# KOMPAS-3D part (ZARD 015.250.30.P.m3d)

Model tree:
1. Плоскость XY
2. Плоскость ZX
3. Плоскость ZY
4. Ось X
5. Ось Y
6. Ось Z
7. Начало координат
8. Смещенная плоскость:1
     Расстояние = 100
9. Смещенная плоскость:2
     Расстояние = 100
10. Смещенная плоскость:3
     Расстояние = 105
11. Смещенная плоскость:4
     Расстояние = 105
12. Булева операция:1
13. Булева операция:2
14. Булева операция:3
15. Булева операция:4
16. Булева операция:5
17. Булева операция:6
